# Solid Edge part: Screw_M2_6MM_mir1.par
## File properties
Last saved by: hhakima
Revision: 50
Accuracy: 0.990
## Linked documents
Screw_M2_6MM.par
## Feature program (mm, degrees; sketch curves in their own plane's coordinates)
part copy "CopiedPart_1"
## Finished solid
Body 1: solid body, 24 faces, 41 edges, 20 vertices.
  Faces by surface: plane 10, cone 9, cylinder 3, spline 2
  Edges by curve: circle 15, line 12, intersection 10, spline 4
Bounding box of the edges (mm; curved faces can reach further): 3.800 x 3.800 x 8.000, from (-1.9, -1.9, -8) to (1.9, 1.9, 0).
Cylindrical faces by radius (mm): R0.7402 x1, R1 x1, R1.9 x1
Conical faces (half-angle, radius in mm at the cone's reference point): 45 deg R0.866 x6, 45 deg R1.71 x1, 45 deg R1.9 x1, 55 deg R0.4862 x1
Planar faces by outward normal: +x 1, +z 2, -x 1, -z 2, oblique 4
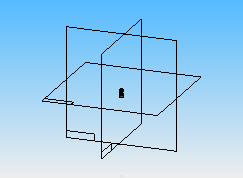
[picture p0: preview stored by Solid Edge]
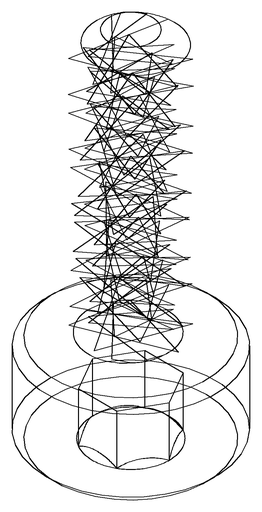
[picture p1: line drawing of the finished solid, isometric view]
